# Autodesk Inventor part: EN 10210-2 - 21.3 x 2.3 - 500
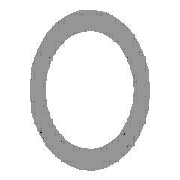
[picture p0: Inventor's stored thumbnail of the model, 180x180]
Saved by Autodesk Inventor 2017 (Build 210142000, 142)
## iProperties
Created: 2017-11
Part Number: EN 10210-2 - 21.3 x 2.3 - 500
Material: Steel, Mild
Description: Pipe
Document SubType Name: Modeling
Standard: DIN
Designer: iusti
Standard Revision: 2006-07
Standards Organization: DIN
Language: en-US
Size Designation: 21.3 x 2.3
Categories: <MemberInstance><Categories><Category DisplayName="Structural Shapes" InternalName="089c4875-fa83-4c05-b084-43b9cc11f5ed" Mnemonic="GRDR"><CategoryParameter Dis
Stock Number: 21.3 x 2.3
Density: 7.85 g/cm^3
Appearance: Semi-Polished
IsCustomPart: 1
G_L: 500.000 mm
G_W: 21.300 mm
G_H: 21.300 mm
_CCFamilyMember: 1
_CCFamilyDisplayName: DIN EN 10210-2 - Pipe
_FrameMemberDoc: Frame Member File
_Version: 15.0.0
_GetPNFromCC: 1
Author: iusti
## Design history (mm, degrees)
node "Start plane"
node "End plane"
sketch "Sketch"
  geometry: C1 r 8.35 at (0, 0); C2 r 10.65 at (0, 0); 2 further points
  constraints: 3 coincident, 2 centre point
  dimensions: "d0" = 21.3 diameter of C2 (= G_H); "d1" = 2.3 radial gap between concentric circles of C2 C1 (= G_T)
extrude "Body" new body sketch "Sketch" stored distance "d2" = 500 (= G_L); taper "d3" = 0 deg
node "Driven Length"
  sketch "Sketch3"
    geometry: L1 (0, 0)-(10, 0) reference
    constraints: 2 end point, 1 horizontal
  workplane "Work Plane3"
  sketch "Sketch4"
    geometry: L1 (-2, 0)-(12, 0) reference; L2 (-2, 500)-(12, 500) reference
    dimensions: "d7" = 500 distance between parallel lines of L1 L2 (derived)
body "Solid1"
other parameters: "G_H" = 21.3 [user parameter; used in 1 equation term], "G_T" = 2.3 [user parameter; used in 1 equation term], "G_L" = 500 (= d7) [user parameter; used in 1 equation term], "G_OFFSET_START" = 0 [user parameter; used in 1 equation term], "G_OFFSET_END" = 0 [user parameter; used in 1 equation term], "d4" = 0 (computed from G_OFFSET_START), "d6" = 90 deg
